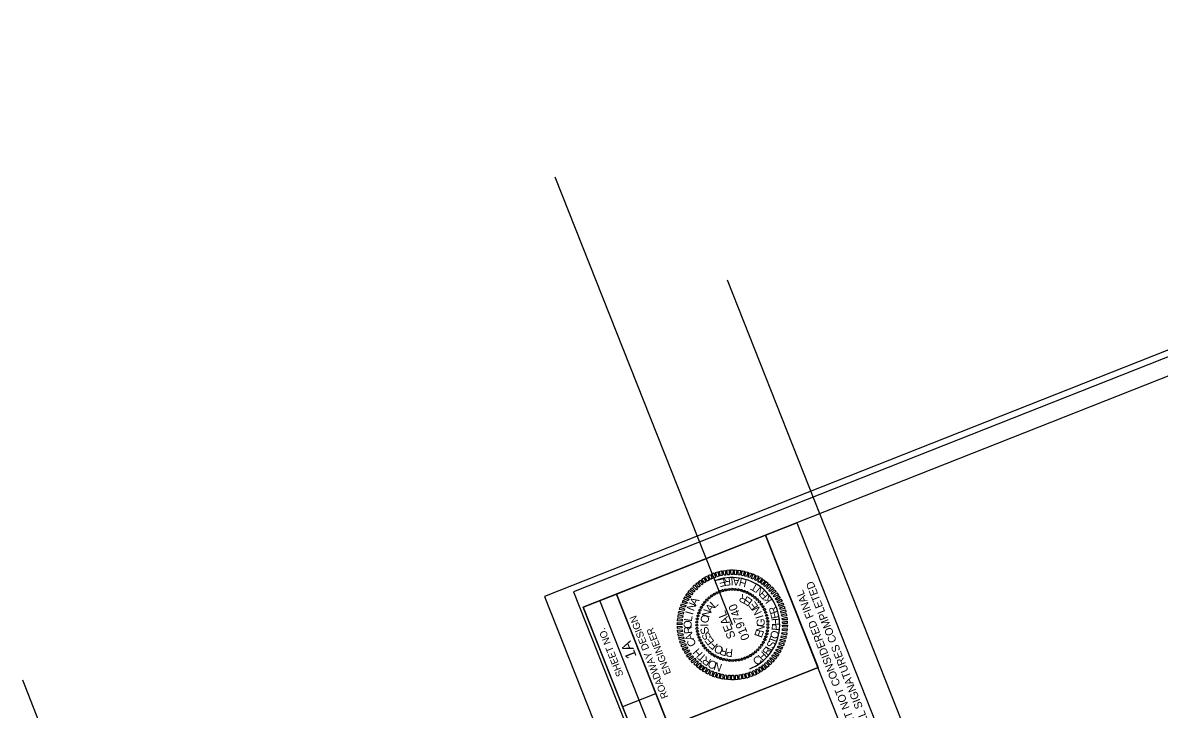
# Model space of a CAD drawing. Extents: x 1247235 to 1260080, y 742320 to 754020.
# Drawn here: x 1251024 to 1254628, y 751842 to 754020 of the extents above; entities that cross this region are included whole.
import ezdxf

# ---------------------------------------------------------------- set-up
doc = ezdxf.new("R2010")
doc.units = 0
for name, color, linetype in [('Scratch_Level_0', 7, 'Continuous'), ('Scratch_Level_1', 7, 'Continuous'), ('Scratch_Level_2', 7, 'Continuous'), ('Sheet Data Field CELL', 7, 'Continuous'), ('Sheet Plan CELL', 7, 'Continuous'), ('Sheet Plot Border Inside CELL', 7, 'Continuous'), ('Sheet Plot Border Outside CELL', 7, 'Continuous'), ('Sheet Professional Seal CELL', 7, 'Continuous'), ('Sheet Sticker Exception Certification CELL', 7, 'Continuous')]:
    doc.layers.add(name, color=color, linetype=linetype)

msp = doc.modelspace()

# ---------------------------------------------------------------- linework, layer by layer
at = {"layer": 'Scratch_Level_0'}
msp.add_arc((1253273.9, 752109.8), 150.1, 291.5743, 111.5743, dxfattribs=at)
at = {"layer": 'Scratch_Level_1'}
for p, q in [((1253273.9, 752109.8), (1252712, 753530.8)), ((1253273.9, 752109.8), (1253273.9, 752109.8)), ((1251585.7, 750513), (1251023.8, 751934))]:
    msp.add_line(p, q, dxfattribs=at)
at = {"layer": 'Scratch_Level_2'}
msp.add_line((1255936.1, 746431.7), (1253258.3, 753203.9), dxfattribs=at)
at = {"layer": 'Sheet Plan CELL'}
for p, q in [((1253239, 751366.8), (1252906.5, 752207.8)), ((1253239, 751366.8), (1252906.5, 752207.8)), ((1253186.5, 751346), (1252854, 752187)), ((1253072.7, 751787.4), (1253545.5, 751974.3)), ((1252926.1, 751850.9), (1253031.2, 751892.5))]:
    msp.add_line(p, q, dxfattribs=at)
for points in [[(1252801.2, 752166.1), (1255294.6, 745860.4), (1259708.5, 747605.8), (1257215.2, 753911.5)], [(1253072.7, 751787.4), (1252906.5, 752207.8), (1253379.4, 752394.8), (1253545.7, 751974.4)], [(1253133.7, 751325.2), (1252801.2, 752166.1), (1252906.5, 752207.8), (1253239, 751366.8)]]:
    msp.add_lwpolyline(points, close=True, dxfattribs=at)
at = {"layer": 'Sheet Plot Border Inside CELL'}
msp.add_lwpolyline([(1259974.2, 746964.6), (1257204.9, 753968.2), (1252769.9, 752214.5), (1255539.2, 745211)], close=True, dxfattribs=at)
at = {"layer": 'Sheet Plot Border Outside CELL'}
msp.add_lwpolyline([(1260079.9, 746943.2), (1257281.5, 754020.3), (1252678.4, 752200.2), (1255476.7, 745123.1)], close=True, dxfattribs=at)
at = {"layer": 'Sheet Professional Seal CELL'}
for p, q in [((1253216.6, 752207), (1253216.6, 752207)), ((1253225.1, 752211.8), (1253225.1, 752211.8)), ((1253234.2, 752215.6), (1253234.2, 752215.6)), ((1253243.7, 752218.6), (1253243.7, 752218.6)), ((1253253.3, 752220.7), (1253253.3, 752220.7)), ((1253262.8, 752222.3), (1253262.8, 752222.3)), ((1253272.7, 752222.9), (1253272.7, 752222.9)), ((1253282.6, 752222.4), (1253282.6, 752222.4)), ((1253292.4, 752221.5), (1253292.4, 752221.5)), ((1253302, 752219.2), (1253302, 752219.2)), ((1253311.6, 752216.5), (1253311.6, 752216.5)), ((1253320.5, 752212.7), (1253320.5, 752212.7)), ((1253329.5, 752208.3), (1253329.5, 752208.3)), ((1253180.7, 752173.6), (1253180.7, 752173.6)), ((1253186.7, 752181.6), (1253186.7, 752181.6)), ((1253193.2, 752189), (1253193.2, 752189)), ((1253200.3, 752195.7), (1253200.3, 752195.7)), ((1253208.1, 752201.7), (1253208.1, 752201.7)), ((1253337.7, 752203.1), (1253337.7, 752203.1)), ((1253345.6, 752197), (1253345.6, 752197)), ((1253353, 752190.5), (1253353, 752190.5)), ((1253359.7, 752183.5), (1253359.7, 752183.5)), ((1253365.7, 752175.7), (1253365.7, 752175.7)), ((1253164.5, 752138), (1253164.5, 752138)), ((1253167.3, 752147.5), (1253167.3, 752147.5)), ((1253171, 752156.5), (1253171, 752156.5)), ((1253175.4, 752165.5), (1253175.4, 752165.5)), ((1253371, 752167.1), (1253371, 752167.1)), ((1253375.8, 752158.6), (1253375.8, 752158.6)), ((1253379.7, 752149.5), (1253379.7, 752149.5)), ((1253382.7, 752140), (1253382.7, 752140)), ((1253160.8, 752108.7), (1253160.8, 752108.7)), ((1253161.3, 752118.6), (1253161.3, 752118.6)), ((1253161.4, 752098.8), (1253161.4, 752098.8)), ((1253162.3, 752128.4), (1253162.3, 752128.4)), ((1253273.9, 752109.8), (1253273.9, 752109.8)), ((1253384.8, 752130.5), (1253384.8, 752130.5)), ((1253386.4, 752120.9), (1253386.4, 752120.9)), ((1253386.4, 752101.1), (1253386.4, 752101.1)), ((1253386.9, 752111), (1253386.9, 752111)), ((1253163, 752089.2), (1253163, 752089.2)), ((1253165.1, 752079.7), (1253165.1, 752079.7)), ((1253168.1, 752070.2), (1253168.1, 752070.2)), ((1253376.8, 752063.2), (1253376.8, 752063.2)), ((1253380.5, 752072.2), (1253380.5, 752072.2)), ((1253383.2, 752081.7), (1253383.2, 752081.7)), ((1253385.5, 752091.3), (1253385.5, 752091.3)), ((1253171.9, 752061.1), (1253171.9, 752061.1)), ((1253176.8, 752052.6), (1253176.8, 752052.6)), ((1253182.1, 752044), (1253182.1, 752044)), ((1253188.1, 752036.2), (1253188.1, 752036.2)), ((1253194.7, 752029.2), (1253194.7, 752029.2)), ((1253354.5, 752030.7), (1253354.5, 752030.7)), ((1253361, 752038.1), (1253361, 752038.1)), ((1253367.1, 752046.1), (1253367.1, 752046.1)), ((1253372.3, 752054.2), (1253372.3, 752054.2)), ((1253202.1, 752022.7), (1253202.1, 752022.7)), ((1253210.1, 752016.6), (1253210.1, 752016.6)), ((1253218.2, 752011.4), (1253218.2, 752011.4)), ((1253227.2, 752007), (1253227.2, 752007)), ((1253236.2, 752003.2), (1253236.2, 752003.2)), ((1253245.7, 752000.5), (1253245.7, 752000.5)), ((1253255.3, 751998.2), (1253255.3, 751998.2)), ((1253265.2, 751997.3), (1253265.2, 751997.3)), ((1253275, 751996.8), (1253275, 751996.8)), ((1253285, 751997.4), (1253285, 751997.4)), ((1253294.5, 751999), (1253294.5, 751999)), ((1253304.1, 752001.1), (1253304.1, 752001.1)), ((1253313.5, 752004.1), (1253313.5, 752004.1)), ((1253322.6, 752007.9), (1253322.6, 752007.9)), ((1253331.1, 752012.7), (1253331.1, 752012.7)), ((1253339.7, 752018), (1253339.7, 752018)), ((1253347.5, 752024), (1253347.5, 752024))]:
    msp.add_line(p, q, dxfattribs=at)
for points in [[(1253225.7, 752262.3), (1253220.7, 752276.1), (1253227.8, 752278.4), (1253230.9, 752263.9)], [(1253236.1, 752265.3), (1253232.1, 752279.1), (1253239.5, 752281.1), (1253241.6, 752266.2)], [(1253247.5, 752267.8), (1253244, 752281.4), (1253251.7, 752282.8), (1253252.5, 752267.9)], [(1253258.6, 752269.1), (1253256.2, 752283.1), (1253263.7, 752284.4), (1253263.6, 752269.1)], [(1253269.9, 752269.9), (1253268.5, 752284.3), (1253276.1, 752284.2), (1253275.2, 752269.3)], [(1253280.7, 752269.3), (1253280.4, 752284.2), (1253288.1, 752283.6), (1253286.2, 752269.1)], [(1253292, 752269), (1253292.5, 752283), (1253300.3, 752282.4), (1253297, 752268)], [(1253303, 752267.5), (1253304.6, 752281.7), (1253312.2, 752279.8), (1253308.1, 752265.6)], [(1253313.8, 752264.5), (1253316.5, 752278.6), (1253324.1, 752277.1), (1253318.9, 752263.4)], [(1253168.1, 752229.2), (1253157.7, 752239.8), (1253163.2, 752244.7), (1253171.7, 752233)], [(1253176.9, 752236.5), (1253166.7, 752248), (1253173.2, 752252), (1253180.7, 752239.7)], [(1253185.9, 752243), (1253176.7, 752254.6), (1253183.3, 752258.7), (1253189.8, 752246)], [(1253195.2, 752248.8), (1253186.9, 752261.3), (1253193.8, 752264.7), (1253199.9, 752251.7)], [(1253204.8, 752254.1), (1253197.7, 752267), (1253204.7, 752270.2), (1253209.6, 752256.5)], [(1253215.1, 752258.4), (1253209.1, 752271.8), (1253216.2, 752274.6), (1253220.2, 752260.4)], [(1253324.3, 752261.4), (1253328.1, 752275.5), (1253335.4, 752273.1), (1253329.2, 752260)], [(1253335.1, 752257.2), (1253339.5, 752271.3), (1253346.4, 752268), (1253339.8, 752255.2)], [(1253345.2, 752253.2), (1253350.7, 752266.1), (1253357.8, 752263), (1253349.7, 752250.4)], [(1253355, 752247.4), (1253361.5, 752260.4), (1253368.1, 752256.5), (1253359.3, 752244.5)], [(1253364.4, 752241.9), (1253372, 752253.9), (1253378.1, 752250), (1253368.7, 752238.3)], [(1253373.3, 752234.8), (1253381.5, 752247), (1253387.4, 752241.8), (1253377.3, 752231.8)], [(1253139, 752195.9), (1253126.1, 752202.6), (1253130.6, 752209), (1253141.9, 752200)], [(1253145.4, 752204.7), (1253133.1, 752212.6), (1253137.8, 752219.1), (1253148.4, 752209.3)], [(1253152.4, 752213.8), (1253140.5, 752222.6), (1253145.9, 752227.9), (1253155.4, 752217.9)], [(1253159.8, 752221.5), (1253148.6, 752231.4), (1253154.3, 752236.8), (1253163.6, 752225.4)], [(1253381.8, 752227.8), (1253390.9, 752239.1), (1253396.4, 752233.8), (1253385.5, 752223.9)], [(1253389.9, 752220.3), (1253399.9, 752230.6), (1253404.9, 752225.3), (1253393.2, 752215.6)], [(1253397.3, 752211.4), (1253407.9, 752221.2), (1253412.4, 752215.4), (1253400.5, 752207.6)], [(1253404, 752202.4), (1253415.4, 752212), (1253419.7, 752205.5), (1253406.8, 752198.4)], [(1253124.3, 752165.6), (1253110, 752169.9), (1253113.1, 752176.9), (1253125.9, 752170.9)], [(1253128.7, 752176.1), (1253115.3, 752181.2), (1253118.3, 752188.2), (1253130.8, 752180.5)], [(1253133.3, 752186.4), (1253120.1, 752192.3), (1253124, 752198.9), (1253136.3, 752190.9)], [(1253410.2, 752193.3), (1253422.3, 752201.9), (1253425.7, 752195.3), (1253412.9, 752188.5)], [(1253415.5, 752183.7), (1253428, 752191.3), (1253431.6, 752184.6), (1253418.1, 752179)], [(1253420.7, 752173.7), (1253433.8, 752180.1), (1253436.4, 752173.1), (1253422.4, 752168.6)], [(1253115.7, 752133.7), (1253101.5, 752134.6), (1253102.6, 752142.3), (1253116.6, 752138.6)], [(1253118.1, 752144.1), (1253103, 752146.6), (1253105.3, 752153.8), (1253118.8, 752149.7)], [(1253121, 752155.1), (1253106.4, 752158.3), (1253108.8, 752165.6), (1253122.3, 752160.3)], [(1253424.4, 752163.6), (1253438, 752168.9), (1253440.5, 752162), (1253426.2, 752158.5)], [(1253427.9, 752152.9), (1253441.9, 752157.4), (1253443.3, 752150), (1253429.1, 752147.5)], [(1253430.2, 752142.2), (1253444.4, 752145.6), (1253446, 752138.2), (1253431.6, 752136.9)], [(1253432.1, 752130.6), (1253446.6, 752133.9), (1253447.7, 752126.1), (1253432.8, 752125.8)], [(1253114.4, 752111.1), (1253099.3, 752110.7), (1253099.5, 752117.6), (1253114, 752116.5)], [(1253114.4, 752100.2), (1253100.1, 752098.3), (1253099.7, 752105.6), (1253114.1, 752105.2)], [(1253114.7, 752122.1), (1253100.2, 752122.5), (1253100.6, 752130.1), (1253115.1, 752127.6)], [(1253433.1, 752097.6), (1253447.5, 752097.2), (1253447.1, 752089.6), (1253432.6, 752092)], [(1253433.3, 752108.5), (1253448.4, 752108.9), (1253448.2, 752102.1), (1253433.8, 752103.2)], [(1253433.4, 752119.5), (1253447.6, 752121.4), (1253448.1, 752114.1), (1253433.7, 752114.5)], [(1253115.6, 752089.1), (1253101.2, 752085.8), (1253100, 752093.6), (1253114.9, 752093.9)], [(1253117.5, 752077.5), (1253103.4, 752074.1), (1253101.7, 752081.4), (1253116.2, 752082.8)], [(1253119.8, 752066.8), (1253105.9, 752062.3), (1253104.4, 752069.7), (1253118.7, 752072.2)], [(1253426.8, 752064.6), (1253441.4, 752061.4), (1253438.9, 752054.1), (1253425.4, 752059.4)], [(1253429.7, 752075.6), (1253444.7, 752073.1), (1253442.5, 752065.9), (1253429, 752070)], [(1253432.1, 752086), (1253446.3, 752085.1), (1253445.2, 752077.4), (1253431.2, 752081.1)], [(1253123.3, 752056.1), (1253109.7, 752050.8), (1253107.2, 752057.7), (1253121.6, 752061.2)], [(1253127.1, 752046), (1253113.9, 752039.6), (1253111.4, 752046.6), (1253125.3, 752051.1)], [(1253132.3, 752036), (1253119.8, 752028.4), (1253116.1, 752035.1), (1253129.7, 752040.7)], [(1253137.5, 752026.4), (1253125.4, 752017.8), (1253122.1, 752024.4), (1253134.9, 752031.2)], [(1253414.5, 752033.3), (1253427.7, 752027.4), (1253423.8, 752020.8), (1253411.4, 752028.7)], [(1253419.1, 752043.6), (1253432.5, 752038.5), (1253429.5, 752031.5), (1253417, 752039.2)], [(1253423.4, 752054.1), (1253437.7, 752049.8), (1253434.7, 752042.8), (1253421.9, 752048.8)], [(1253143.8, 752017.3), (1253132.3, 752007.7), (1253128.1, 752014.2), (1253141, 752021.3)], [(1253150.5, 752008.3), (1253139.8, 751998.5), (1253135.4, 752004.3), (1253147.3, 752012.1)], [(1253157.9, 751999.4), (1253147.9, 751989.1), (1253142.9, 751994.4), (1253154.5, 752004.1)], [(1253165.9, 751991.9), (1253156.8, 751980.6), (1253151.3, 751985.9), (1253162.2, 751995.8)], [(1253379.6, 751990.5), (1253390.1, 751979.9), (1253384.5, 751975), (1253376, 751986.7)], [(1253388, 751998.2), (1253399.1, 751988.3), (1253393.5, 751982.9), (1253384.2, 751994.3)], [(1253395.3, 752005.9), (1253407.3, 751997.1), (1253401.8, 751991.8), (1253392.3, 752001.8)], [(1253402.4, 752015), (1253414.7, 752007), (1253410, 752000.6), (1253399.3, 752010.4)], [(1253408.8, 752023.8), (1253421.6, 752017), (1253417.1, 752010.7), (1253405.8, 752019.7)], [(1253174.5, 751984.9), (1253166.2, 751972.7), (1253160.3, 751977.8), (1253170.4, 751987.9)], [(1253183.4, 751977.8), (1253175.7, 751965.8), (1253169.6, 751969.7), (1253179, 751981.4)], [(1253192.8, 751972.3), (1253186.3, 751959.3), (1253179.7, 751963.2), (1253188.5, 751975.2)], [(1253202.6, 751966.5), (1253197, 751953.6), (1253190, 751956.7), (1253198.1, 751969.3)], [(1253212.6, 751962.5), (1253208.3, 751948.4), (1253201.4, 751951.7), (1253208, 751964.5)], [(1253223.5, 751958.3), (1253219.6, 751944.2), (1253212.4, 751946.6), (1253218.5, 751959.7)], [(1253233.9, 751955.2), (1253231.3, 751941.1), (1253223.6, 751942.6), (1253228.9, 751956.3)], [(1253244.8, 751952.2), (1253243.1, 751938), (1253235.6, 751939.9), (1253239.7, 751954.1)], [(1253311.6, 751954.4), (1253315.7, 751940.5), (1253308.2, 751938.6), (1253306.2, 751953.5)], [(1253322.1, 751957.4), (1253327, 751943.6), (1253320, 751941.3), (1253316.9, 751955.8)], [(1253332.6, 751961.3), (1253338.6, 751947.9), (1253331.5, 751945.1), (1253327.6, 751959.3)], [(1253343, 751965.6), (1253350, 751952.7), (1253343.1, 751949.5), (1253338.1, 751963.2)], [(1253352.5, 751970.9), (1253360.8, 751958.4), (1253354, 751955), (1253347.9, 751968)], [(1253361.8, 751976.7), (1253371, 751965.1), (1253364.4, 751961), (1253357.9, 751973.7)], [(1253370.9, 751983.2), (1253381, 751971.7), (1253374.6, 751967.7), (1253367.1, 751980)], [(1253255.7, 751950.7), (1253255.2, 751936.7), (1253247.5, 751937.3), (1253250.8, 751951.7)], [(1253267, 751950.4), (1253267.3, 751935.5), (1253259.6, 751936.1), (1253261.6, 751950.6)], [(1253277.9, 751949.8), (1253279.2, 751935.3), (1253271.7, 751935.5), (1253272.6, 751950.4)], [(1253289.2, 751950.6), (1253291.6, 751936.6), (1253284.1, 751935.3), (1253284.1, 751950.6)], [(1253300.3, 751951.9), (1253303.7, 751938.3), (1253296, 751936.9), (1253295.2, 751951.8)]]:
    msp.add_lwpolyline(points, close=True, dxfattribs=at)
for centre, major_axis in [((1253216.5, 752207), (-1.65, 2.79)), ((1253225.2, 752211.7), (-1.4, 2.92)), ((1253234.2, 752215.5), (-1.14, 3.03)), ((1253243.6, 752218.6), (-0.87, 3.12)), ((1253253.2, 752220.8), (-0.59, 3.18)), ((1253262.9, 752222.2), (-0.31, 3.22)), ((1253272.7, 752222.7), (-0.03, 3.24)), ((1253282.6, 752222.4), (0.25, 3.23)), ((1253292.4, 752221.2), (0.53, 3.2)), ((1253302, 752219.1), (0.81, 3.14)), ((1253311.4, 752216.3), (1.08, 3.06)), ((1253320.5, 752212.6), (1.34, 2.95)), ((1253329.3, 752208.1), (1.59, 2.82)), ((1253337.7, 752202.9), (1.83, 2.67)), ((1253180.8, 752173.7), (-2.67, 1.83)), ((1253186.7, 752181.5), (-2.5, 2.06)), ((1253193.3, 752188.8), (-2.31, 2.27)), ((1253200.5, 752195.6), (-2.11, 2.46)), ((1253208.2, 752201.6), (-1.88, 2.64)), ((1253345.5, 752197), (2.06, 2.5)), ((1253352.9, 752190.4), (2.27, 2.31)), ((1253359.6, 752183.3), (2.46, 2.11)), ((1253365.7, 752175.5), (2.64, 1.88)), ((1253371, 752167.3), (2.79, 1.65)), ((1253164.6, 752138), (-3.14, 0.81)), ((1253167.4, 752147.4), (-3.06, 1.08)), ((1253171.1, 752156.5), (-2.95, 1.34)), ((1253175.6, 752165.3), (-2.82, 1.59)), ((1253375.7, 752158.6), (2.92, 1.4)), ((1253379.5, 752149.5), (3.03, 1.14)), ((1253382.6, 752140.1), (3.12, 0.87)), ((1253384.8, 752130.6), (3.18, 0.59)), ((1253161, 752108.7), (-3.24, -0.03)), ((1253161.4, 752118.6), (-3.23, 0.25)), ((1253161.5, 752098.9), (-3.22, -0.31)), ((1253162.5, 752128.3), (-3.2, 0.53)), ((1253386.2, 752120.8), (3.22, 0.31)), ((1253386.4, 752101.1), (3.23, -0.25)), ((1253386.7, 752111), (3.24, 0.03)), ((1253162.9, 752089.1), (-3.18, -0.59)), ((1253165.2, 752079.5), (-3.12, -0.87)), ((1253168.2, 752070.2), (-3.03, -1.14)), ((1253172.1, 752061.1), (-2.92, -1.4)), ((1253376.6, 752063.2), (2.95, -1.34)), ((1253380.3, 752072.3), (3.06, -1.08)), ((1253383.2, 752081.7), (3.14, -0.81)), ((1253385.2, 752091.4), (3.2, -0.53)), ((1253176.7, 752052.4), (-2.79, -1.65)), ((1253182.1, 752044.2), (-2.64, -1.88)), ((1253188.1, 752036.4), (-2.46, -2.11)), ((1253194.9, 752029.2), (-2.27, -2.31)), ((1253202.2, 752022.7), (-2.06, -2.5)), ((1253347.3, 752024.1), (2.11, -2.46)), ((1253354.5, 752030.8), (2.31, -2.27)), ((1253361.1, 752038.2), (2.5, -2.06)), ((1253367, 752046), (2.67, -1.83)), ((1253372.2, 752054.4), (2.82, -1.59)), ((1253210.1, 752016.8), (-1.83, -2.67)), ((1253218.4, 752011.5), (-1.59, -2.82)), ((1253227.2, 752007.1), (-1.34, -2.95)), ((1253236.3, 752003.4), (-1.08, -3.06)), ((1253245.8, 752000.5), (-0.81, -3.14)), ((1253255.4, 751998.5), (-0.53, -3.2)), ((1253265.2, 751997.3), (-0.25, -3.23)), ((1253275, 751997), (0.03, -3.24)), ((1253284.8, 751997.5), (0.31, -3.22)), ((1253294.6, 751998.9), (0.59, -3.18)), ((1253304.2, 752001.1), (0.87, -3.12)), ((1253313.5, 752004.2), (1.14, -3.03)), ((1253322.6, 752008), (1.4, -2.92)), ((1253331.3, 752012.7), (1.65, -2.79)), ((1253339.5, 752018.1), (1.88, -2.64))]:
    msp.add_ellipse(centre, major_axis=major_axis, ratio=0.999708, dxfattribs=at)
at = {"layer": 'Sheet Sticker Exception Certification CELL'}
for p, q in [((1253379.4, 752394.8), (1253478.2, 752433.8)), ((1253478.2, 752433.8), (1253810.7, 751592.9)), ((1253711.9, 751553.8), (1253379.4, 752394.8))]:
    msp.add_line(p, q, dxfattribs=at)

# ---------------------------------------------------------------- texts
at = {"layer": 'Sheet Data Field CELL'}
msp.add_text('1A ', height=33.9, rotation=111.5743, dxfattribs=at).set_placement((1252971, 752010.2))
at = {"layer": 'Sheet Plan CELL'}
for s, height, p in [('ROADWAY DESIGN', 22.603, (1253071.2, 751881.1)), ('SHEET NO.', 22.6, (1252929.1, 751950.8)), ('ENGINEER', 22.6, (1253079.9, 751956.7))]:
    msp.add_text(s, height=height, rotation=111.5743, dxfattribs=at).set_placement(p)
at = {"layer": 'Sheet Professional Seal CELL'}
for s, height, rotation, p in [('E', 24.8, 193.7569, (1253249.5, 752258.4)), ('R', 24.8, 186.8304, (1253267.6, 752260.3)), ('I', 24.8, 183.31, (1253276.8, 752260.4)), ('A', 24.8, 175.1242, (1253298.2, 752258.5)), ('H', 24.7, 165.8794, (1253321.8, 752252.6)), ('R', 25.4, 154.0558, (1253324.8, 752198.2)), ('T', 24.8, 150.1375, (1253358.7, 752234.3)), ('N', 24.8, 140.2057, (1253378.9, 752217.8)), ('E', 24.8, 133.6228, (1253390.6, 752205)), ('K', 24.8, 125.9522, (1253402.2, 752188.6)), ('N', 25.4, 67.3933, (1253151.4, 752151.7)), ('A', 25.4, 60.1915, (1253158.8, 752168.9)), ('A', 25.4, 53.3346, (1253206.3, 752147.5)), ('L', 25.4, 43.9752, (1253217.5, 752161.3)), ('019740', 26.99, 111.5743, (1253329.5, 752067.2)), ('E', 25.4, 144.6984, (1253340.5, 752187.3)), ('E', 25.4, 125.9861, (1253357.5, 752168.3)), ('R', 24.8, 109.5806, (1253419.2, 752149.2)), ('L', 25.4, 81.7952, (1253145.1, 752119.2)), ('I', 25.4, 74.5945, (1253148.4, 752140.1)), ('O', 25.4, 81.4078, (1253197.3, 752113.9)), ('N', 25.4, 72.051, (1253200.1, 752131.2)), ('SEAL', 26.99, 111.5743, (1253284.9, 752071.6)), ('N', 25.4, 116.6307, (1253368.2, 752148.6)), ('I', 25.4, 107.2755, (1253373.1, 752134.3)), ('E', 24.8, 102.9976, (1253422.8, 752132.3)), ('O', 25.4, 88.9955, (1253144.6, 752097.7)), ('R', 25.4, 96.1954, (1253147, 752082.4)), ('I', 25.4, 90.764, (1253197.6, 752104.4)), ('S', 25.4, 109.4747, (1253201.8, 752085.2)), ('N', 25.4, 79.2083, (1253372.8, 752084.1)), ('G', 25.4, 88.5646, (1253376, 752103.8)), ('H', 24.8, 93.7528, (1253424.5, 752108.1)), ('P', 24.8, 87.1698, (1253423.3, 752090.8)), ('A', 25.4, 110.5947, (1253153.2, 752064.5)), ('C', 25.4, 117.7942, (1253160.9, 752048.5)), ('S', 25.4, 118.83, (1253208, 752070.2)), ('E', 25.4, 128.1854, (1253218.1, 752057.5)), ('E', 25.4, 69.8512, (1253366.5, 752067.1)), ('T', 24.7, 70.1685, (1253411.2, 752048)), ('O', 24.8, 76.4653, (1253417.1, 752063.4)), ('H', 25.4, 132.1938, (1253181.9, 752020)), ('F', 25.4, 137.5414, (1253229.7, 752046.6)), ('O', 25.4, 156.2556, (1253247.5, 752037.7)), ('R', 25.4, 165.614, (1253260.6, 752034.4)), ('P', 25.4, 174.9732, (1253276.7, 752033)), ('H', 24.8, 43.6935, (1253369.2, 751993.3)), ('R', 24.7, 52.9383, (1253386.7, 752010.1)), ('I', 24.8, 59.8647, (1253397.9, 752024.4)), ('S', 24.7, 63.3852, (1253402.9, 752032.2)), ('T', 25.4, 139.3941, (1253194.2, 752009.1)), ('R', 25.4, 146.5949, (1253209, 751998.5)), ('O', 25.4, 153.7961, (1253227.7, 751989.2)), ('N', 25.4, 160.9978, (1253243.6, 751984.4)), ('C', 24.8, 34.8208, (1253350.1, 751980))]:
    msp.add_text(s, height=height, rotation=rotation, dxfattribs=at).set_placement(p)
at = {"layer": 'Sheet Sticker Exception Certification CELL'}
for s, p in [('UNLESS ALL SIGNATURES COMPLETED', (1253765.8, 751652.9)), ('DOCUMENT NOT CONSIDERED FINAL', (1253720.4, 751659.6))]:
    msp.add_text(s, height=24.863, rotation=111.5743, dxfattribs=at).set_placement(p)

doc.saveas('drawing.dxf')
